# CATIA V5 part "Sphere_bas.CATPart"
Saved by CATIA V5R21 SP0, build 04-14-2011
Part number: Sphere_bas_droite
Bounding box of the stored display mesh (mm): x 0 to 13.5, y -23 to 23, z -16.25 to 0
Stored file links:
  D:\FRANCE\Stage\CAO\CAO final\3D impression\Sphere_bas.CATPart
  D:\FRANCE\Stage\CAO\CAO final\3D impression\Sphere_assemblage.CATProduct
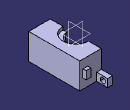
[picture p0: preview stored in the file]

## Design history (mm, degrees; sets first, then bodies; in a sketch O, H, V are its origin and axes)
External parameters (linked from other documents)
  External.Radius = 6 mm
  External.Length = 5.25 mm
Body1 (main body)
  Sketch1 on xy-plane, origin (0, 0, 0), H (1, 0, 0), V (0, 1, 0)
    line L1 (13.5, 16) -> (13.5, -16)
    line L2 (13.5, -16) -> (-13.5, -16)
    line L3 (-13.5, -16) -> (-13.5, 16)
    line L4 (-13.5, 16) -> (13.5, 16)
    length L1 = 32
    length L4 = 27
    vertical: L1 V, L3 V
    horizontal: L2 H, L4 H
    equidistance: L1 L3 O, L2 L4 O
  Pad1: profile Sketch1, direction (0, 0, -1), length 16.25 {= External.Radius +External.Length +5mm}
  Sketch2 on yz-plane, origin (0, 0, 0), H (0, 1, 0), V (0, 0, 1)
    arc A1 centre (0, -5.25) radius 6.5 from (0, -11.75) to (3.8324, 0) ccw
    point P1 (0, -5.25)
    line L1 (0, 0) -> (0, -11.75)
    point P3 (3.8324, 0)
    line L2 (3.8324, 0) -> (0, 0)
    radius A1 = 6.5 {= External.Radius +0.5mm}
    distance P1 H = 5.25 {= External.Length}
    vertical: L1 V
    horizontal: L2 H
    coincidence: V P1, L1 V, P3 H, L2 H
  Groove1: profile Sketch2, axis Sketch2.L1, angle 360
  Split1: SplitPlane yz-plane
  Sketch3 on face of Split1, origin (0, 13.367, -13.79), H (0, 1, 0), V (0, 0, -1)
    point P1 (-3.367, -1.54)
    reference projected line E1 (2.633, 2.46) -> (2.633, -13.79) from edge [face of Split1 | face of Pad1 from Sketch1.L4]
    reference projected line E2 (2.633, 2.46) -> (-29.367, 2.46) from edge [end face of Pad1 | face of Split1]
    distance P1 E1 = 6
    distance P1 E2 = 4
  Hole1: placed by Sketch3, at (0, 10, -12.25) direction (1, 0, 0), diameter 3.5, depth 5
  Mirror1: of Hole1, about zx-plane
  Sketch4 on face of Pad1 from Sketch1.L2, origin (0, -16, 0), H (1, 0, 0), V (0, 0, 1)
    point P1 (0, -16.25)
    line L1 (0, -16.25) -> (3, -16.25)
    line L2 (3, -16.25) -> (3, -11.25)
    line L3 (3, -11.25) -> (0, -11.25)
    point P4 (0, -11.25)
    line L4 (0, -11.25) -> (0, -16.25)
    reference projected line E1 (-13.5, -16.25) -> (13.5, -16.25) from edge [end face of Pad1 | face of Pad1 from Sketch1.L2]
    length L2 = 5
    length L3 = 3
    coincidence: P1 V, P4 V, L1 E1, L4 V
    horizontal: L1 H, L3 H
    vertical: L2 V, L4 V
  Pad2: profile Sketch4, direction (0, -1, 0), length 7
  Mirror2: of Pad2, about zx-plane
  Sketch5 on face of Mirror2, origin (0, -26.2195, -7.3063), H (0, 1, 0), V (0, 0, -1)
    point P1 (6.2195, 6.4437)
    reference projected line E1 (42.2195, 8.9437) -> (10.2195, 8.9437) from edge [face of Mirror2 | face of Mirror2]
    reference projected line E2 (3.2195, 3.9437) -> (3.2195, 8.9437) from edge [face of Mirror2 | end face of Pad2]
    distance P1 E1 = 2.5
    distance P1 E2 = 3
  Hole2: placed by Sketch5, at (0, -20, -13.75) direction (1, 0, 0), diameter 3.2, through (limit type 3)
  Mirror3: of Hole2, about zx-plane
  Sketch6 on face of Pad1 from Sketch1.L4, origin (0, 16, 0), H (-1, 0, 0), V (0, 0, 1)
    point P1 (-10, -7.75)
    line L1 (-8.5, -5.25) -> (-8.5, -10.25)
    line L2 (-8.5, -10.25) -> (-11.5, -10.25)
    line L3 (-11.5, -10.25) -> (-11.5, -5.25)
    line L4 (-11.5, -5.25) -> (-8.5, -5.25)
    reference projected line E1 (-13.5, -16.25) -> (13.5, -16.25) from edge [face of Mirror2 | face of Pad1 from Sketch1.L4]
    length L2 = 3
    length L3 = 5
    distance P1 E1 = 8.5
    distance P1 V = 10
    vertical: L1 V, L3 V
    horizontal: L2 H, L4 H
    equidistance: L1 L3 P1, L2 L4 P1
  Pad3: profile Sketch6, direction (0, 1, 0), length 2
  Mirror4: of Pad3, about zx-plane
  Sketch7 on start face of Pad1, origin (0, 0, 0), H (1, 0, 0), V (0, 1, 0)
    arc A1 centre (0, 0) radius 8 from (0, -8) to (0, 8) ccw
    point P1 (0, 8)
    line L1 (0, 8) -> (0, -8)
    radius A1 = 8
    coincidence: P1 V
    vertical: L1 V
  Pocket1: profile Sketch7, direction (0, 0, -1), length 2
